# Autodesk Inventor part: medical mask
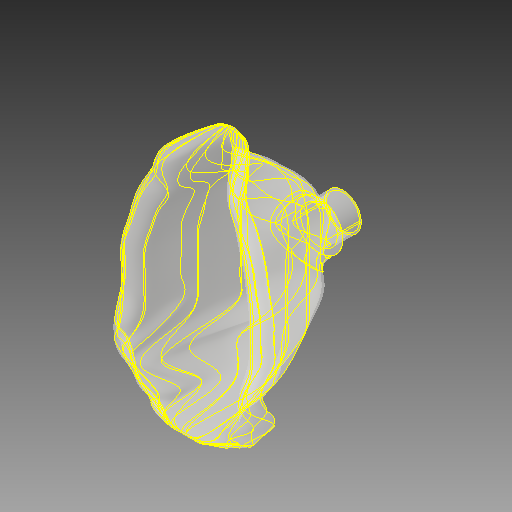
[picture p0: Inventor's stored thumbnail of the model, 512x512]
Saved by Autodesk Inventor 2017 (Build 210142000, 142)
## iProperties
Created: 2020-03
Part Number: medical mask
Material: Generic
Document SubType Name: Modeling
Designer: user
Density: 1 g/cm^3
Appearance: Default
Author: user
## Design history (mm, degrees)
feature "Composite1"
body "Srf1"
